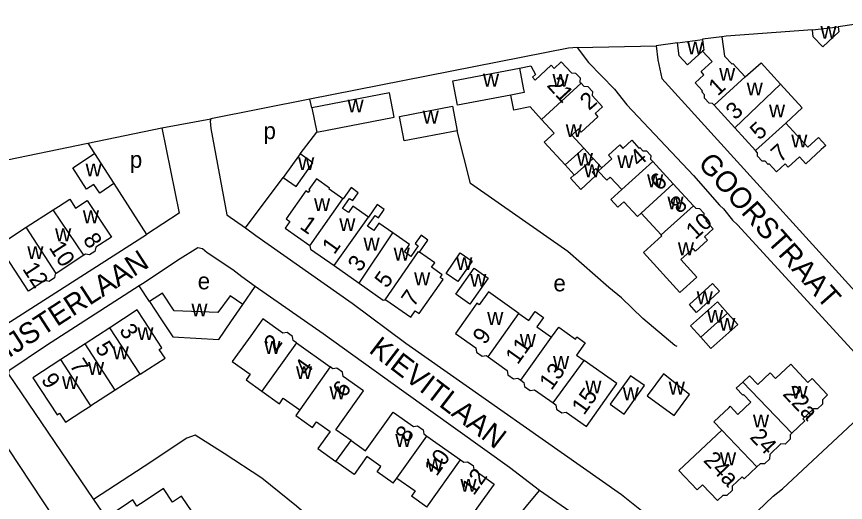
# Model space of a CAD drawing. Extents: x 161775 to 163181, y 382878 to 383925.
# Drawn here: x 162569.5 to 162768.1, y 383767.3 to 383883.7 of the extents above; entities that cross this region are included whole.
import ezdxf

# ---------------------------------------------------------------- set-up
doc = ezdxf.new("R2010")
doc.units = 0
for name, color, linetype in [('BLT_Basislijn', 7, 'Continuous'), ('BLT_Bebouwing', 7, 'Continuous'), ('BLT_Centroide', 7, 'Continuous'), ('BLT_Huisnummer', 7, 'Continuous'), ('BLT_Huisnummer_ tussenligend', 7, 'Continuous'), ('BLT_Onderverdeling_panden', 7, 'Continuous'), ('BLT_Straatnaam', 7, 'Continuous'), ('BLT_Vlakafsluiter', 7, 'Continuous')]:
    doc.layers.add(name, color=color, linetype=linetype)

msp = doc.modelspace()

# ---------------------------------------------------------------- linework, layer by layer
at = {"layer": 'BLT_Basislijn'}
for p, q in [((162739.49, 383878.97), (162738.52, 383878.82)), ((162640.24, 383861.84), (162639.73, 383863.88)), ((162637.41, 383850.81), (162641.38, 383855.94)), ((162538.07, 383843.34), (162586.53, 383853.37)), ((162624.33, 383833.08), (162633.39, 383845.1)), ((162601.3, 383815.41), (162598.86, 383819.14)), ((162623.65, 383814.66), (162626.67, 383819.02)), ((162684.47, 383757.78), (162694.78, 383770.14))]:
    msp.add_line(p, q, dxfattribs=at)
for points in [[(162783.07, 383883.67), (162782.8, 383883.64), (162766.41, 383881.22)], [(162760.2, 383880.51), (162739.49, 383878.97)], [(162703.8, 383876.24), (162701.71, 383876.13), (162639.73, 383863.88)], [(162703.8, 383876.24), (162706.56, 383872.66), (162712.77, 383866.28), (162715.7, 383862.52), (162731.68, 383845.59), (162737.91, 383838.46), (162738.87, 383837.6), (162741.07, 383834.89), (162742.28, 383833.77), (162778.38, 383794.39)], [(162727.87, 383877.41), (162722.74, 383876.69)], [(162722.74, 383876.69), (162723.12, 383873.32), (162724.1, 383868.83)], [(162785.46, 383801.22), (162782.97, 383804.02), (162724.1, 383868.83)], [(162639.73, 383863.88), (162616.01, 383859.15)], [(162616.01, 383859.15), (162615.88, 383858.59), (162616.05, 383856.86), (162619.83, 383836.2), (162624.33, 383833.08)], [(162586.53, 383853.37), (162604.3, 383856.98)], [(162604.3, 383856.98), (162608.4, 383836.57), (162600.6, 383831.49)], [(162727.8, 383804.59), (162727.24, 383804.85), (162719.58, 383811.34), (162714.47, 383816.3), (162711.38, 383818.77), (162701.54, 383827.35), (162678.22, 383843.68), (162675.04, 383856.31)], [(162586.53, 383853.37), (162588.1, 383850.9)], [(162592.77, 383843.64), (162600.6, 383831.49)], [(162624.33, 383833.08), (162626.77, 383831.18), (162649.91, 383815.03), (162662.77, 383805.45), (162714.41, 383769.18), (162720.06, 383764.71), (162723.13, 383762.72), (162734.54, 383754.59), (162735.88, 383754.49), (162750.82, 383768.72), (162752.99, 383770.53), (162769.85, 383786.24), (162778.38, 383794.39)], [(162457.24, 383828.18), (162456.19, 383826.97), (162456.29, 383825.76), (162464.18, 383808.68), (162467.33, 383801.31), (162490.73, 383757.23), (162491.46, 383756.16), (162491.87, 383755.97), (162496.17, 383755.95), (162523.13, 383781.04), (162527.33, 383784.63), (162600.6, 383831.49)], [(162626.67, 383819.02), (162623.44, 383821.28), (162621.3, 383822.96), (162615.12, 383827.09), (162614, 383828.05), (162612.89, 383828.23), (162608.04, 383825.25), (162600, 383819.88), (162598.86, 383819.14)], [(162598.86, 383819.14), (162576.63, 383804.83), (162567.59, 383798.8), (162567.53, 383797.97), (162587.89, 383767.93)], [(162694.78, 383770.14), (162687.59, 383775.59), (162662.26, 383793.72), (162642.94, 383807.64), (162626.67, 383819.02)], [(162629.33, 383686.98), (162612.03, 383713.4), (162608.08, 383719.09), (162606.08, 383723.33), (162602.63, 383728.87), (162600, 383732.8), (162593.38, 383742.71), (162593.11, 383743.45), (162589.47, 383749.07), (162586.52, 383753.27), (162583.22, 383758.28), (162581.69, 383758.34), (162581.31, 383759.17), (162559.03, 383792.81)], [(162641.71, 383761.9), (162636.51, 383766.36), (162628.2, 383773.06), (162619.23, 383778.97), (162612.25, 383783.38), (162610.25, 383782.63), (162600, 383775.89), (162587.89, 383767.93)], [(162702.01, 383731.7), (162705.9, 383734.11), (162710.38, 383736.7), (162725.71, 383746.87), (162726.11, 383747.68), (162712.67, 383757.71), (162694.78, 383770.14)], [(162587.89, 383767.93), (162590.67, 383763.91), (162590.04, 383763.37), (162590.67, 383761.93), (162592.93, 383758.6), (162593.15, 383757.86), (162600, 383748), (162612.73, 383728.83), (162613.91, 383728.47), (162614.8, 383727.56), (162621.78, 383716.76), (162638.46, 383692.44)]]:
    msp.add_lwpolyline(points, dxfattribs=at)
at = {"layer": 'BLT_Bebouwing'}
for p, q in [((162760.2, 383880.51), (162766.41, 383881.22)), ((162727.87, 383877.41), (162733.84, 383878.2)), ((162687.91, 383864.87), (162675.15, 383862.41)), ((162661.22, 383859.73), (162673.9, 383862.18)), ((162673.9, 383862.18), (162675.04, 383856.31)), ((162741.62, 383856.98), (162736.63, 383862.42)), ((162640.24, 383861.84), (162641.38, 383855.94)), ((162641.38, 383855.94), (162659.98, 383859.53)), ((162746.59, 383851.56), (162741.62, 383856.98)), ((162705.4, 383852.13), (162707.62, 383849.7)), ((162588.1, 383850.9), (162592.77, 383843.64)), ((162637.41, 383850.81), (162633.39, 383845.1)), ((162709.72, 383847.41), (162707.62, 383849.7)), ((162721.93, 383848.98), (162726.83, 383843.62)), ((162703.12, 383845.74), (162700.97, 383848.11)), ((162726.83, 383843.62), (162731.71, 383838.29)), ((162578.26, 383837.33), (162579.53, 383838.15)), ((162723.92, 383831.34), (162719.13, 383836.57)), ((162732.13, 383837.83), (162732.22, 383837.74)), ((162639.77, 383828.79), (162639.78, 383828.75)), ((162585.58, 383826.48), (162578.93, 383822.15)), ((162645.56, 383824), (162651.59, 383819.76)), ((162620.84, 383810.52), (162623.65, 383814.66)), ((162657.94, 383815.83), (162657.98, 383815.83)), ((162591.77, 383809.08), (162585.88, 383805.26)), ((162585.88, 383805.26), (162580.07, 383801.48)), ((162636.53, 383805.51), (162644.59, 383799.77)), ((162713.33, 383795.72), (162705.49, 383801.29)), ((162599.08, 383797.98), (162593.1, 383794.15)), ((162593.1, 383794.15), (162587.29, 383790.42)), ((162667.8, 383783.16), (162675.86, 383777.43)), ((162659.74, 383771.87), (162660.62, 383773.1)), ((162667.79, 383766.13), (162664.08, 383768.77))]:
    msp.add_line(p, q, dxfattribs=at)
for points in [[(162766.41, 383881.22), (162766.55, 383879.99), (162762.67, 383876.44), (162760.41, 383878.84), (162760.2, 383880.51)], [(162738.52, 383878.82), (162733.83, 383878.25), (162733.84, 383878.2)], [(162738.52, 383878.82), (162739.12, 383874.19), (162740.96, 383872.26), (162741.16, 383872.45), (162744.05, 383869.22)], [(162733.84, 383875.39), (162730.28, 383872.11), (162728.29, 383874.28), (162727.87, 383877.41)], [(162736.63, 383862.42), (162736.24, 383862.85), (162735.47, 383862.89), (162734.33, 383864.12), (162734.37, 383864.94), (162733.7, 383865.67), (162733.89, 383865.84), (162732.1, 383867.8), (162734.2, 383869.74), (162733.52, 383870.48), (162736.18, 383872.91), (162733.84, 383875.39)], [(162689.97, 383871.32), (162692.72, 383871.85), (162693.82, 383869.78), (162693.12, 383869.14), (162693.75, 383868.46), (162697.62, 383872), (162698.3, 383871.26), (162700.02, 383872.84), (162702.45, 383870.2), (162703.44, 383870.15), (162704.53, 383868.96), (162704.49, 383867.98), (162704.75, 383867.69)], [(162744.05, 383869.22), (162747.91, 383872.55), (162752.54, 383867.49)], [(162675.15, 383862.41), (162674.02, 383868.24), (162689.97, 383871.32)], [(162704.75, 383867.69), (162705.42, 383866.96), (162706.38, 383866.92), (162707.49, 383865.72), (162707.44, 383864.73), (162709.9, 383862.04), (162708.12, 383860.42), (162708.8, 383859.68), (162704.79, 383856.01), (162704.11, 383856.74), (162702.52, 383855.29), (162705.4, 383852.13)], [(162752.54, 383867.49), (162757.76, 383861.77), (162753.81, 383858.16)], [(162659.98, 383859.53), (162658.84, 383865.43), (162640.24, 383861.84)], [(162695.3, 383859.03), (162692.53, 383862.06), (162688.61, 383861.22), (162687.91, 383864.87)], [(162675.04, 383856.31), (162662.35, 383853.86), (162661.22, 383859.73)], [(162700.97, 383848.11), (162695.87, 383853.55), (162698.31, 383855.74), (162695.3, 383859.03)], [(162753.81, 383858.16), (162759.08, 383852.39), (162761.62, 383854.72), (162763.39, 383852.79), (162762.3, 383851.79), (162758.62, 383848.41), (162757.12, 383850.05), (162754.42, 383847.57), (162753.7, 383848.35), (162751.62, 383846.45), (162749.82, 383848.42), (162749.61, 383848.22), (162748.9, 383848.99), (162748.12, 383849.03), (162747.03, 383850.21), (162747.07, 383851.04), (162746.59, 383851.56)], [(162709.72, 383847.41), (162712.12, 383849.61), (162711.35, 383850.45), (162714.03, 383852.9), (162714.77, 383852.09), (162716.88, 383854.02), (162718.61, 383852.12), (162718.83, 383852.32), (162719.55, 383851.53), (162720.46, 383851.49), (162721.46, 383850.4), (162721.42, 383849.53), (162721.93, 383848.98)], [(162592.77, 383843.64), (162589.38, 383841.36), (162587.98, 383843.43), (162586.23, 383842.28), (162582.93, 383847.45), (162588.1, 383850.9)], [(162633.39, 383845.1), (162636.48, 383842.92), (162640.5, 383848.63), (162637.41, 383850.81)], [(162708.88, 383846.65), (162708.31, 383847.26), (162707.42, 383846.4), (162708.24, 383845.5), (162704.66, 383842.25), (162702.23, 383844.93), (162703.12, 383845.74)], [(162714.54, 383842.22), (162711.72, 383845.22), (162710.92, 383844.47), (162708.88, 383846.65)], [(162647.65, 383840.02), (162644.35, 383842.34), (162644.49, 383842.54), (162641.3, 383844.78), (162639.52, 383842.24), (162639.71, 383842.1), (162639.31, 383841.53), (162638.79, 383841.89), (162634.07, 383835.18), (162634.96, 383834.55), (162633.84, 383832.96), (162639.77, 383828.79)], [(162653.82, 383835.59), (162650.05, 383838.24), (162648.98, 383836.72), (162647.57, 383837.71), (162649.27, 383840.12), (162650.02, 383839.59), (162651.34, 383841.47), (162649.62, 383842.68), (162647.72, 383839.97), (162647.65, 383840.02)], [(162719.13, 383836.57), (162718.24, 383835.75), (162715, 383839.29), (162713.57, 383837.98), (162711.9, 383839.81), (162714.54, 383842.22)], [(162579.53, 383838.15), (162582.21, 383839.9), (162583.56, 383837.8), (162586.38, 383839.63), (162592.24, 383830.82), (162588.46, 383828.41), (162588.24, 383827.4), (162586.95, 383826.56), (162586.01, 383826.76), (162585.58, 383826.48)], [(162659.66, 383831.83), (162656.31, 383834.19), (162655.05, 383832.4), (162653.6, 383833.42), (162655.4, 383835.98), (162656.16, 383835.44), (162657.57, 383837.44), (162655.85, 383838.65), (162653.82, 383835.59)], [(162731.71, 383838.29), (162732.22, 383837.74), (162733.13, 383837.7), (162734.17, 383836.56), (162734.13, 383835.72), (162734.84, 383834.95), (162734.62, 383834.75), (162736.39, 383832.8), (162734.31, 383830.9), (162735.02, 383830.11), (162732.17, 383827.48), (162731.59, 383828.11), (162728.69, 383825.45)], [(162571.79, 383833.19), (162578.26, 383837.33)], [(162558.52, 383832.65), (162561.57, 383834.63), (162565.27, 383828.95), (162571.79, 383833.19)], [(162666.01, 383827.21), (162668.06, 383830.12), (162666.39, 383831.3), (162664.97, 383829.28), (162665.72, 383828.76), (162663.94, 383826.22), (162662.42, 383827.28), (162663.65, 383829.03), (162659.66, 383831.83)], [(162728.41, 383817.53), (162719.68, 383827.13), (162724.09, 383831.15), (162723.92, 383831.34)], [(162639.78, 383828.75), (162639.92, 383827.97), (162645.56, 383824)], [(162578.93, 383822.15), (162578.73, 383822.02), (162578.52, 383821.05), (162577.25, 383820.22), (162576.24, 383820.44), (162572.29, 383817.87), (162565.76, 383827.93), (162562.83, 383826.02)], [(162657.79, 383815.8), (162657.98, 383815.83), (162663.93, 383811.65), (162664.99, 383813.16), (162665.92, 383812.5), (162668.8, 383816.59), (162671.68, 383820.7), (162671.01, 383821.17), (162671.47, 383821.83), (162668.94, 383823.61), (162669.67, 383824.64), (162666.01, 383827.21)], [(162728.69, 383825.45), (162732.52, 383821.27), (162728.41, 383817.53)], [(162651.59, 383819.76), (162657.34, 383815.72), (162657.79, 383815.8)], [(162623.65, 383814.66), (162620.68, 383816.79), (162617.68, 383812.73), (162607.19, 383813.2), (162604.45, 383817.39), (162601.3, 383815.41)], [(162689.85, 383812.51), (162682.54, 383817.7), (162680.34, 383814.6), (162679.8, 383814.98), (162677.55, 383811.81), (162674.65, 383807.73), (162679.52, 383804.27), (162679.7, 383803.24), (162681.01, 383802.3), (162681.97, 383802.47), (162682.46, 383802.11)], [(162601.3, 383815.41), (162604.04, 383811.24), (162606.9, 383806.9), (162617.95, 383806.27), (162620.84, 383810.52)], [(162739.87, 383812.59), (162737.43, 383815.3), (162731.01, 383809.54)], [(162599.08, 383797.98), (162605.04, 383801.8), (162603.66, 383803.92), (162604.26, 383804.31), (162603.24, 383805.88), (162600, 383810.86), (162598.37, 383813.37), (162591.77, 383809.08)], [(162689.85, 383812.51), (162692.21, 383810.83), (162693.74, 383812.98), (162695.75, 383811.56), (162694.18, 383809.35), (162697.65, 383806.88)], [(162733.45, 383806.82), (162735.86, 383804.13), (162742.29, 383809.9), (162739.87, 383812.59)], [(162636.53, 383805.51), (162635.77, 383806.05), (162635.61, 383807.03), (162634.28, 383807.98), (162633.28, 383807.81), (162628.48, 383811.23), (162625.58, 383807.16), (162621.16, 383801), (162625.41, 383797.96), (162624.45, 383796.61), (162628.24, 383793.9)], [(162697.65, 383806.88), (162699.41, 383809.22), (162703.39, 383806.39), (162703.75, 383806.9), (162705.74, 383805.49), (162703.67, 383802.58), (162705.49, 383801.29)], [(162731.01, 383809.54), (162733.45, 383806.82)], [(162580.07, 383801.48), (162573.39, 383797.14), (162579.17, 383788.23), (162579.76, 383788.62), (162581.15, 383786.49), (162585.36, 383789.19), (162587.29, 383790.42)], [(162682.46, 383802.11), (162687.06, 383798.85), (162687.23, 383797.82), (162688.58, 383796.86), (162689.63, 383797.04), (162690.32, 383796.55)], [(162649.64, 383782.06), (162645.97, 383784.68), (162652.62, 383793.99), (162647.77, 383797.44), (162647.59, 383798.49), (162646.25, 383799.45), (162645.27, 383799.28), (162644.59, 383799.77)], [(162743.49, 383796.1), (162745.08, 383797.61), (162747.08, 383795.51), (162750.04, 383798.32), (162751.37, 383796.92), (162754.99, 383800.36), (162759.11, 383796.01), (162760.1, 383796.94), (162763.84, 383793), (162762.61, 383791.83), (162762.58, 383790.79), (162761.38, 383789.66), (162760.42, 383789.68), (162757.93, 383787.32), (162758.42, 383786.8), (162755.3, 383783.83)], [(162690.32, 383796.55), (162691.05, 383796.03), (162691.22, 383795.04), (162692.55, 383794.09), (162693.6, 383794.27), (162698.04, 383791.12)], [(162711.75, 383790.79), (162715.07, 383788.42), (162717.97, 383792.5), (162719.92, 383795.24), (162716.59, 383797.61), (162711.75, 383790.79)], [(162724.47, 383798.1), (162720.6, 383792.79), (162727.06, 383788.09), (162730.74, 383793.13), (162724.47, 383798.1)], [(162698.04, 383791.12), (162698.68, 383790.66), (162698.86, 383789.61), (162700.13, 383788.7), (162701.19, 383788.88), (162706.04, 383785.44), (162713.33, 383795.72)], [(162738.49, 383784.61), (162736.61, 383786.6), (162740.23, 383790.04), (162740.51, 383790.3), (162742.36, 383788.35), (162745.43, 383791.26), (162743.67, 383793.12), (162743.52, 383792.97), (162741.94, 383794.64), (162743.49, 383796.1)], [(162628.24, 383793.9), (162632.45, 383790.91), (162633.39, 383792.23), (162637.33, 383789.43)], [(162637.33, 383789.43), (162636.37, 383788.09), (162640.41, 383785.21), (162641.35, 383786.53), (162644.58, 383784.22), (162641.68, 383780.15), (162646.01, 383777.06)], [(162649.64, 383782.06), (162653.1, 383779.59), (162659.75, 383788.9), (162664.61, 383785.44), (162665.53, 383785.6), (162666.9, 383784.62), (162667.06, 383783.69), (162667.8, 383783.16)], [(162746.88, 383775.76), (162743.88, 383772.92), (162743.39, 383773.43), (162740.96, 383771.13), (162740.93, 383770.08), (162739.67, 383768.88), (162738.72, 383768.9), (162737.45, 383767.7), (162733.86, 383771.48), (162732.59, 383770.27), (162728.22, 383774.88), (162738.49, 383784.61)], [(162755.3, 383783.83), (162754.89, 383783.44), (162754.86, 383782.39), (162753.65, 383781.24), (162752.65, 383781.27), (162749.96, 383778.71), (162749.93, 383777.65), (162748.72, 383776.5), (162747.68, 383776.53), (162746.88, 383775.76)], [(162659.74, 383771.87), (162655.89, 383774.61), (162656.74, 383775.84), (162653.38, 383778.24), (162650.33, 383773.97), (162646.01, 383777.06)], [(162675.86, 383777.43), (162676.64, 383776.88), (162677.52, 383777.02), (162678.86, 383776.07), (162679.02, 383775.13), (162683.89, 383771.66), (162680.99, 383767.59), (162677.53, 383762.74)], [(162660.62, 383773.1), (162664.96, 383770), (162664.08, 383768.77)], [(162611.07, 383764.32), (162610.9, 383764.57), (162611.5, 383764.97), (162608.96, 383768.75), (162606.83, 383767.33), (162604.63, 383770.6), (162600, 383767.5), (162598.31, 383766.37), (162597.32, 383767.85), (162596.25, 383767.13), (162592.1, 383764.35), (162595.82, 383758.8), (162598.08, 383760.32), (162600.36, 383756.91)]]:
    msp.add_lwpolyline(points, dxfattribs=at)
for points in [[(162675.77, 383827.08), (162678.68, 383825.1), (162675.2, 383820.23), (162672.39, 383822.1)], [(162679.13, 383823.35), (162682.48, 383820.97), (162678.06, 383814.75), (162674.71, 383817.13)], [(162730.71, 383814.68), (162736.26, 383819.71), (162737.92, 383817.85), (162732.4, 383812.8)]]:
    msp.add_lwpolyline(points, close=True, dxfattribs=at)
at = {"layer": 'BLT_Onderverdeling_panden'}
for p, q in [((162689.97, 383871.32), (162690.88, 383866.6)), ((162736.63, 383862.42), (162744.05, 383869.22)), ((162690.88, 383866.6), (162691.09, 383865.49)), ((162704.75, 383867.69), (162695.3, 383859.03)), ((162741.62, 383856.98), (162752.54, 383867.49)), ((162691.09, 383865.49), (162687.91, 383864.87)), ((162746.59, 383851.56), (162753.81, 383858.16)), ((162700.97, 383848.11), (162705.4, 383852.13)), ((162714.54, 383842.22), (162721.93, 383848.98)), ((162709.72, 383847.41), (162708.88, 383846.65)), ((162719.13, 383836.57), (162726.83, 383843.62)), ((162639.78, 383828.75), (162647.65, 383840.02)), ((162585.58, 383826.48), (162578.26, 383837.33)), ((162645.56, 383824), (162653.82, 383835.59)), ((162578.93, 383822.15), (162571.79, 383833.19)), ((162651.59, 383819.76), (162659.66, 383831.83)), ((162682.46, 383802.11), (162689.85, 383812.51)), ((162733.45, 383806.82), (162739.87, 383812.59)), ((162599.08, 383797.98), (162591.77, 383809.08)), ((162690.32, 383796.55), (162697.65, 383806.88)), ((162593.1, 383794.15), (162585.88, 383805.26)), ((162636.53, 383805.51), (162628.24, 383793.9)), ((162587.29, 383790.42), (162580.07, 383801.48)), ((162698.04, 383791.12), (162705.49, 383801.29)), ((162644.59, 383799.77), (162637.33, 383789.43)), ((162743.49, 383796.1), (162755.3, 383783.83)), ((162746.88, 383775.76), (162738.49, 383784.61)), ((162660.62, 383773.1), (162667.8, 383783.16)), ((162646.01, 383777.06), (162649.64, 383782.06)), ((162667.79, 383766.13), (162675.86, 383777.43))]:
    msp.add_line(p, q, dxfattribs=at)
for points in [[(162733.84, 383878.2), (162734.14, 383875.66), (162733.84, 383875.39)], [(162707.62, 383849.7), (162703.18, 383845.66), (162703.12, 383845.74)], [(162723.92, 383831.35), (162731.71, 383838.29)], [(162657.79, 383815.8), (162665.8, 383827.36), (162666.01, 383827.21)]]:
    msp.add_lwpolyline(points, dxfattribs=at)
at = {"layer": 'BLT_Vlakafsluiter'}
for p, q in [((162703.8, 383876.24), (162722.74, 383876.69)), ((162604.3, 383856.98), (162616.01, 383859.15))]:
    msp.add_line(p, q, dxfattribs=at)

# ---------------------------------------------------------------- texts
at = {"layer": 'BLT_Centroide'}
for s, p in [('w', (162762.12, 383878.35)), ('w', (162730.19, 383874.6)), ('w', (162737.84, 383868.31)), ('w', (162681.23, 383866.88)), ('w', (162697.9, 383866.84)), ('w', (162744.45, 383864.78)), ('w', (162648.78, 383860.69)), ('w', (162749.79, 383859.53)), ('w', (162666.79, 383858.03)), ('p', (162628.64, 383854.32)), ('w', (162701.08, 383854.78)), ('w', (162755.13, 383852.31)), ('p', (162596.6, 383847.42)), ('w', (162703.74, 383847.94)), ('w', (162713.42, 383847.36)), ('w', (162585.99, 383845.39)), ('w', (162636.94, 383846.88)), ('w', (162705.44, 383845.17)), ('w', (162720.58, 383842.78)), ('w', (162725.45, 383837.47)), ('w', (162640.75, 383837.06)), ('w', (162585.34, 383834.14)), ('w', (162646.8, 383832.27)), ('w', (162578.69, 383829.84)), ('w', (162652.61, 383827.59)), ('w', (162572.03, 383825.55)), ('w', (162659.83, 383825.22)), ('w', (162727.95, 383826.48)), ('w', (162674.83, 383822.94)), ('w', (162664.73, 383819.3)), ('e', (162612.87, 383818.32)), ('w', (162678.17, 383818.94)), ('e', (162698.13, 383817.83)), ('w', (162732.46, 383814.76)), ('w', (162611.36, 383811.84)), ('w', (162682.25, 383809.78)), ('w', (162734.94, 383810.3)), ('w', (162737.87, 383808.38)), ('w', (162598.41, 383806.16)), ('w', (162690.06, 383804.53)), ('w', (162592.48, 383801.55)), ('w', (162628.84, 383802.86)), ('w', (162586.58, 383797.83)), ('w', (162698.03, 383799.25)), ('w', (162636.42, 383796.83)), ('w', (162580.34, 383794.41)), ('w', (162644.45, 383791.98)), ('w', (162705.78, 383793.38)), ('w', (162714.74, 383791.76)), ('w', (162725.76, 383793.09)), ('w', (162755.18, 383792.09)), ('w', (162745.95, 383785.22)), ('w', (162660.22, 383780.55)), ('w', (162738.04, 383776.16)), ('w', (162667.8, 383774.66)), ('w', (162675.84, 383769.8))]:
    msp.add_text(s, height=4, dxfattribs=at).set_placement(p)
at = {"layer": 'BLT_Huisnummer'}
for s, rotation, p in [('21', 312.454, (162696.37, 383867.07)), ('1', 42.5061, (162737.52, 383864.49)), ('2', 41.3121, (162706.66, 383861.04)), ('7', 42.5152, (162752.51, 383848.56)), ('4', 41.3121, (162718.63, 383847.51)), ('10', 42.4782, (162732.13, 383830.07)), ('1', 324.8914, (162637.12, 383833.02)), ('8', 302.9005, (162585.23, 383830.24)), ('1', 54.5307, (162645.6, 383826.47)), ('12', 303.0663, (162570.72, 383823.24)), ('7', 54.8919, (162664.62, 383813.89)), ('3', 303.0038, (162593.93, 383808.47)), ('9', 54.6156, (162681.7, 383804.85)), ('2', 54.4969, (162631.66, 383803.24)), ('9', 302.9942, (162575.2, 383796.66)), ('6', 54.5582, (162648.14, 383792.17)), ('15', 54.6179, (162705.45, 383787.99)), ('22a', 313.4758, (162752.89, 383793.09)), ('8', 54.4719, (162663.18, 383781.39)), ('24', 313.4847, (162744.99, 383782.75)), ('24a', 313.4847, (162733.88, 383777.19)), ('12', 54.5582, (162679.03, 383768.73))]:
    msp.add_text(s, height=4, rotation=rotation, dxfattribs=at).set_placement(p)
at = {"layer": 'BLT_Huisnummer_ tussenligend'}
for s, rotation, p in [('3', 42.5061, (162741.69, 383858.72)), ('5', 42.5061, (162747.47, 383853.89)), ('6', 41.3121, (162723.46, 383841.72)), ('8', 41.3121, (162728.28, 383836.25)), ('10', 302.9005, (162577.1, 383828.31)), ('3', 54.5307, (162651.77, 383822.24)), ('5', 54.5307, (162658.2, 383818.39)), ('5', 303.0038, (162588.15, 383804.29)), ('11', 54.6156, (162689.56, 383800.1)), ('7', 303.0038, (162582.03, 383800.11)), ('4', 54.4969, (162639.05, 383797.43)), ('13', 54.6156, (162697.66, 383793.94)), ('10', 54.4719, (162670.13, 383773.36))]:
    msp.add_text(s, height=4, rotation=rotation, dxfattribs=at).set_placement(p)
at = {"layer": 'BLT_Straatnaam'}
for s, rotation, p in [('GOORSTRAAT', 311.633, (162732.55, 383848.31)), ('LIJSTERLAAN', 32.9726, (162564.47, 383799.77)), ('KIEVITLAAN', 322.5334, (162653.65, 383803.37))]:
    msp.add_text(s, height=5, rotation=rotation, dxfattribs=at).set_placement(p)

doc.saveas('drawing.dxf')
